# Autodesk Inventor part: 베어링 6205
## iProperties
IsCustomPart: 1
Company: 한국ATC센터
Created: 2014-11
Part Number: 베어링 6205
Material: 강, 연강
Description: 깊은 그루브 볼 베어링
Document SubType Name: Modeling
Standard: KS B 2023
Designer: KYOUNG IL JANG
Standards Organization: KS
Language: ko-KR
Size Designation: 6205 - 25 x 52 x 15
Categories: <MemberInstance><Categories><Category DisplayName="샤프트 부품" InternalName="7f7aeb1f-a693-4053-b835-cee3144e0d98" Mnemonic="SHFT"><Category DisplayName="베어링" Inter
Density: 7.86 g/cm^3
Mass: 129.543 g
Surface Area: 107.326 cm^2
Volume: 16.4813 cm^3
Author: KYOUNG IL JANG
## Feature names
1. IDS_ARRAYBALL[SIMPL:T] [Circular Pattern]
